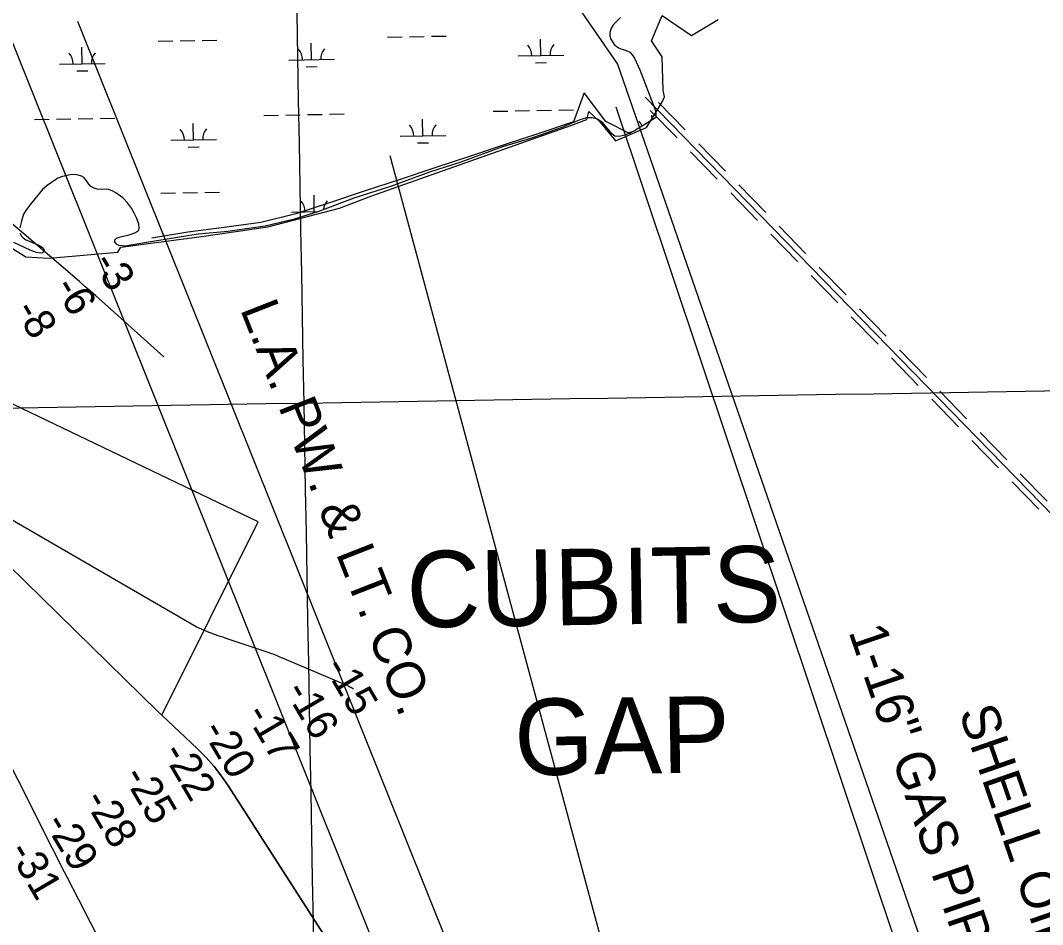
# Model space of a CAD drawing. Extents: x 3914892 to 3953151, y 242587 to 268572.
# Drawn here: x 3939590 to 3941826, y 259377 to 261355 of the extents above; entities that cross this region are included whole.
import ezdxf

# ---------------------------------------------------------------- set-up
doc = ezdxf.new("R2010")
doc.units = 0
for name, color, linetype in [('V-GRID-MAJR', 7, 'Continuous'), ('V-RIVR-EDGE', 7, 'Continuous'), ('V-RIVR-GAP', 7, 'Continuous'), ('V-RIVR-RANG', 7, 'Continuous'), ('V-RRAP-DIKE', 7, 'Continuous'), ('V-RRAP-FSHR', 7, 'Continuous'), ('V-TOPO-DPTH', 7, 'Continuous'), ('V-TOPO-MINR', 7, 'Continuous'), ('V-UTIL-IDEN', 7, 'Continuous'), ('V-UTIL-LINE', 7, 'Continuous'), ('V-WETL-SWMP', 7, 'Continuous')]:
    doc.layers.add(name, color=color, linetype=linetype)

msp = doc.modelspace()

# ---------------------------------------------------------------- linework, layer by layer
at = {"layer": 'V-GRID-MAJR'}
for points in [[(3940428.975, 248401.018), (3940319.725, 254457.832), (3940210.42, 260517.73), (3940101.115, 266577.62), (3940101.059, 266580.712)], [(3918942.3880000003, 260140.297), (3924259.416, 260233.496), (3929576.431, 260327.467), (3934893.433, 260422.212), (3940210.42, 260517.73), (3945527.394, 260614.022), (3950844.353, 260711.087), (3950844.3540000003, 260711.087)]]:
    msp.add_spline(points, degree=3, dxfattribs=at)
at = {"layer": 'V-RIVR-EDGE'}
for points in [[(3940356.2474800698, 260970.12767979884), (3940794.191753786, 261124.67602701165), (3940829.10374867, 261137.76802509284), (3940833.4677480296, 261155.22402253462), (3940858.197077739, 261131.94935927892), (3940891.654406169, 261091.2186985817), (3940960.023729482, 261120.3120276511), (3940981.843726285, 261155.22402253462), (3940994.935724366, 261177.0440193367), (3940999.299723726, 261187.2266845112), (3940996.390390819, 261201.77334904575), (3940994.2083911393, 261275.23400494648), (3940970.9337278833, 261310.14599983), (3940994.2083911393, 261365.42332506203), (3941058.213715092, 261321.78333145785), (3941116.400373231, 261356.69532634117)], [(3939560.530257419, 260863.18542811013), (3939601.4697227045, 260837.69481764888), (3939652.4509436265, 260834.60504668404), (3939803.0772781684, 260847.7365732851), (3939809.256820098, 260858.55077166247), (3939986.146207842, 260881.72405389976), (3940131.365443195, 260903.35245065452), (3940288.171319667, 260944.2919159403), (3940356.242836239, 260970.36185845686)]]:
    msp.add_lwpolyline(points, dxfattribs=at)
at = {"layer": 'V-RRAP-DIKE'}
for points in [[(3942941.2560776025, 259151.36467211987), (3940956.965046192, 261187.10560062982)], [(3941026.768906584, 261097.5817796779), (3940968.1380238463, 261157.73465937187)], [(3941044.67087078, 261115.03174477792), (3940986.039988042, 261175.1846244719)], [(3941114.7167306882, 261007.35296013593), (3941056.084847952, 261067.50583982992)], [(3941132.6186948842, 261024.802925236), (3941073.9868121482, 261084.95580492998)], [(3941202.6645547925, 260917.124140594), (3941144.0326720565, 260977.277020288)], [(3941220.566518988, 260934.5741056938), (3941161.9346362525, 260994.7269853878)], [(3941308.514343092, 260844.3452861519), (3941249.8824603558, 260904.49816584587)], [(3941290.6123788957, 260826.89532105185), (3941231.98049616, 260887.04820074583)], [(3941396.4621671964, 260754.11646660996), (3941337.83028446, 260814.26934630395)], [(3941378.560203, 260736.6665015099), (3941319.928320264, 260796.81938120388)], [(3941484.4099913, 260663.88764706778), (3941425.7781085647, 260724.04052676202)], [(3941466.5080271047, 260646.43768196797), (3941407.876144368, 260706.59056166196)], [(3941572.357815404, 260573.65882752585), (3941513.7259326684, 260633.81170721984)], [(3941554.4558512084, 260556.20886242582), (3941495.823968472, 260616.3617421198)], [(3941660.305639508, 260483.43100798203), (3941601.673756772, 260543.5828876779)], [(3941642.403675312, 260465.98104288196), (3941583.7717925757, 260526.13292257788)], [(3941748.253463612, 260393.20318843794), (3941689.6215808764, 260453.35506813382)], [(3941730.3514994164, 260375.7532233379), (3941671.7196166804, 260435.9051030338)], [(3941836.201287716, 260302.97536889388), (3941777.56940498, 260363.12724859)], [(3941818.29932352, 260285.5254037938), (3941759.667440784, 260345.67728348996)]]:
    msp.add_lwpolyline(points, dxfattribs=at)
at = {"layer": 'V-RRAP-FSHR'}
msp.add_lwpolyline([(3940925.7898332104, 261105.7302865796), (3940870.5634651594, 261133.4090066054), (3940823.340681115, 261196.27851066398), (3940800.136841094, 261132.7393106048), (3940724.2031450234, 261107.55505458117), (3940648.2735449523, 261082.3728465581), (3940572.341896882, 261057.1865425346), (3940496.4102488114, 261032.29924651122), (3940420.4786007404, 261006.81803048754), (3940344.5469526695, 260981.63377446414), (3940268.615304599, 260956.4495184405), (3940192.6836565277, 260931.26526241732), (3940115.619464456, 260912.6100303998), (3940035.722888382, 260901.80683038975), (3939956.418184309, 260891.31697438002), (3939877.5005522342, 260878.21182236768)], dxfattribs=at)
at = {"layer": 'V-TOPO-DPTH'}
for points in [[(3937935.6033522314, 262362.5402043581), (3937946.807549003, 262343.63632242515), (3937958.257643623, 262324.87497740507), (3938066.361568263, 262151.54759992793), (3938132.132563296, 262046.2824872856), (3938198.016029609, 261941.08794122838), (3938264.0682028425, 261835.99924504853), (3938330.2328473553, 261730.98111545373), (3938533.302113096, 261409.237278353), (3938543.3552703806, 261393.41452513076), (3938553.4715195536, 261377.63248157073), (3938563.682406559, 261361.91150250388), (3938573.9563854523, 261346.23123309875), (3938689.531013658, 261170.99052217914), (3938725.5086589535, 261118.47567351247), (3938762.682482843, 261066.8546234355), (3938801.6505746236, 261016.5742712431), (3939215.8425195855, 260521.97311348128), (3939235.1154305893, 260496.93985141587), (3939254.337950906, 260471.8680751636), (3939273.484885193, 260446.73852763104), (3939890.5030939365, 259842.8503603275), (3939899.174331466, 259835.0878290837)], [(3939899.174331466, 259835.0878290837), (3940110.2800000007, 260258.01), (3939485.676288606, 260556.6594979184)], [(3939273.484885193, 260446.73852763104), (3939890.5030939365, 259842.8503603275), (3939899.174331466, 259835.0878290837), (3939977.245341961, 259761.3610688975), (3939995.93333721, 259742.37468959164), (3940013.6277888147, 259722.56399577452), (3940029.8319249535, 259701.51683019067), (3940045.042517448, 259679.64535009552), (3940259.416958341, 259346.02710651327)], [(3939768.654261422, 259332.08815600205), (3939692.0899913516, 259480.36083535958), (3939681.3323571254, 259501.29508046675), (3939670.629942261, 259522.25738085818), (3939660.010356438, 259543.26176417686), (3939649.4459899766, 259564.29420278), (3939601.6381155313, 259659.9443888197), (3939566.333453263, 259728.33550029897)], [(3939768.654261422, 259332.08815600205), (3939692.0899913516, 259480.36083535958), (3939681.3323571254, 259501.29508046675), (3939670.629942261, 259522.25738085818), (3939660.010356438, 259543.26176417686), (3939649.4459899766, 259564.29420278), (3939601.6381155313, 259659.9443888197), (3939566.333453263, 259728.33550029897)]]:
    msp.add_lwpolyline(points, dxfattribs=at)
at = {"layer": 'V-TOPO-MINR'}
for points in [[(3939903.7800000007, 260619.13), (3939766.9304156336, 260741.46724377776), (3939755.026493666, 260752.03635902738), (3939743.0751896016, 260762.5512495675), (3939731.0528123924, 260772.98480304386), (3939718.983053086, 260783.36413181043), (3939193.1441723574, 261232.46224556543)], [(3940110.2800000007, 260258.01), (3939485.676288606, 260556.6594979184)], [(3940259.416958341, 259346.02710651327), (3940045.042517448, 259679.64535009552), (3940029.8319249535, 259701.51683019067), (3940013.6277888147, 259722.56399577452), (3939995.93333721, 259742.37468959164), (3939977.245341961, 259761.3610688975), (3939899.174331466, 259835.0878290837), (3939890.5030939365, 259842.8503603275), (3939273.484885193, 260446.73852763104)], [(3940318.31, 259892.08000000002), (3940314.3937941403, 259894.5625426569), (3940312.4091833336, 259895.75328992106), (3940308.3169462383, 259897.9003167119), (3940306.2093199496, 259898.85659623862), (3940177.4224712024, 259953.51548022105), (3940172.00488143, 259955.82833565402), (3940166.5939002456, 259958.15646144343), (3940161.1928319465, 259960.50749276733), (3940155.798372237, 259962.87379444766), (3940150.379223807, 259965.17489716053), (3940144.9206192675, 259967.37398063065), (3940139.4028305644, 259969.4200352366), (3940133.8455857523, 259971.3640705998), (3940042.2333125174, 260001.9849008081), (3940032.405484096, 260005.32902063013), (3940022.60267381, 260008.74372962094), (3940012.8373907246, 260012.26432236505), (3940003.097125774, 260015.85550427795), (3939974.735562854, 260028.50245078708), (3939542.998862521, 260277.52856744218)], [(3939768.654261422, 259332.08815600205), (3939692.0899913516, 259480.36083535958), (3939681.3323571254, 259501.29508046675), (3939670.629942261, 259522.25738085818), (3939660.010356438, 259543.26176417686), (3939649.4459899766, 259564.29420278), (3939601.6381155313, 259659.9443888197), (3939566.333453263, 259728.33550029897)]]:
    msp.add_lwpolyline(points, dxfattribs=at)
at = {"layer": 'V-UTIL-LINE'}
for p, q in [((3941072.986, 257567.442), (3939526.299, 261421.028)), ((3941262.278, 257498.559), (3939715.592, 261352.14800000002)), ((3942171.498, 257345.774), (3940893.606, 261165.00400000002)), ((3941339.742, 257565.166), (3940398.835, 261058.278))]:
    msp.add_line(p, q, dxfattribs=at)
msp.add_lwpolyline([(3937257.69907959, 266529.8389520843), (3940896.284, 261258.97), (3942305.4820000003, 257189.557), (3945242.894, 251786.949), (3947661.3890917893, 248530.41995604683)], dxfattribs=at)
at = {"layer": 'V-WETL-SWMP'}
for p, q in [((3940393.176292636, 261318.2527012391), (3940425.1711721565, 261318.8251385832)), ((3940441.168611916, 261319.1113572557), (3940473.1634914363, 261319.68379459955)), ((3940489.1609311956, 261319.9700132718), (3940521.1558107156, 261320.54245061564)), ((3940728.7972833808, 261277.82004355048), (3940728.1532913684, 261313.8142830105)), ((3939725.1419090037, 261259.8631133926), (3939724.497916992, 261295.8573528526)), ((3939891.348605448, 261309.27423616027), (3939923.3434849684, 261309.84667350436)), ((3939939.3409247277, 261310.13289217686), (3939971.3358042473, 261310.70532952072)), ((3939987.333244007, 261310.99154819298), (3940019.328123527, 261311.5639855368)), ((3940226.9695961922, 261268.84157847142), (3940226.3256041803, 261304.83581793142)), ((3940176.977596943, 261267.9471451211), (3940276.9615954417, 261269.73601182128)), ((3940678.8052841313, 261276.92561020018), (3940778.78928263, 261278.71447690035)), ((3939675.1499097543, 261258.96868004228), (3939775.1339082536, 261260.75754674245)), ((3940215.2475563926, 261253.1983836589), (3940239.2437160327, 261253.6277116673)), ((3940717.0752435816, 261262.17684873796), (3940741.071403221, 261262.60617674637)), ((3939713.4198692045, 261244.21991858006), (3939737.416028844, 261244.64924658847)), ((3940624.11829016, 261155.85695997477), (3940656.11316968, 261156.42939731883)), ((3940672.11060944, 261156.7156159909), (3940704.1054889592, 261157.28805333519)), ((3940720.1029287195, 261157.57427200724), (3940752.097808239, 261158.1467093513)), ((3940768.0952479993, 261158.43292802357), (3940800.090127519, 261159.00536536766)), ((3939620.462915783, 261137.90002981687), (3939652.457795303, 261138.47246716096)), ((3939668.4552350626, 261138.758685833), (3939700.4501145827, 261139.33112317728)), ((3939716.4475543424, 261139.61734184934), (3939748.4424338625, 261140.1897791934)), ((3939764.439873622, 261140.4759978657), (3939796.434753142, 261141.04843520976)), ((3940122.2906029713, 261146.8784948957), (3940154.2854824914, 261147.45093223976)), ((3940170.282922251, 261147.73715091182), (3940202.277801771, 261148.30958825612)), ((3940218.275241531, 261148.59580692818), (3940250.270121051, 261149.16824427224)), ((3940266.267560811, 261149.4544629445), (3940298.262440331, 261150.0269002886)), ((3940470.458733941, 261102.35763464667), (3940469.8147419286, 261138.35187410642)), ((3940971.828457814, 261136.93275451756), (3940971.642429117, 261147.3303391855)), ((3939968.6310467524, 261093.37916956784), (3939967.98705474, 261129.37340902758)), ((3939918.6390475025, 261092.4847362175), (3940018.6230460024, 261094.2736029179)), ((3940420.466734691, 261101.46320129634), (3940520.4507331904, 261103.25206799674)), ((3940922.29442188, 261110.4416663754), (3940927.821896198, 261110.5405613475)), ((3939956.9090069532, 261077.73597475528), (3939980.9051665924, 261078.1653027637)), ((3940458.7366941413, 261086.71443983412), (3940482.732853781, 261087.14376784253)), ((3939897.299717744, 260976.65246915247), (3939929.294597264, 260977.22490649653)), ((3939945.2920370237, 260977.51112516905), (3939977.2869165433, 260978.08356251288)), ((3939993.2843563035, 260978.36978118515), (3940025.2792358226, 260978.942218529)), ((3940232.920708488, 260936.2198114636), (3940232.276716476, 260972.2140509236)), ((3940182.928709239, 260935.32537811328), (3940241.469185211, 260936.3727567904))]:
    msp.add_line(p, q, dxfattribs=at)
for points in [[(3940902.921, 261360.817), (3940894.651, 261353.166), (3940887.59, 261345.86500000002), (3940882.708, 261337.578), (3940879.7090000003, 261327.986), (3940879.506, 261321.252), (3940882.086, 261313.707), (3940889.102, 261302.05000000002), (3940898.2460000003, 261294.75400000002), (3940905.853, 261291.68), (3940913.578, 261289.527), (3940923.381, 261285.008), (3940928.474, 261279.698), (3940933.514, 261271.787), (3940945.032, 261246.237), (3940977.9220000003, 261161.116), (3940980.301, 261150.812), (3940980.11, 261143.77300000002), (3940979.117, 261141.748), (3940973.3030000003, 261137.858), (3940933.8850000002, 261113.124), (3940912.223, 261103.894), (3940899.6520000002, 261100.817), (3940890.1350000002, 261101.832), (3940883.985, 261106.795), (3940874.855, 261117.761), (3940864.287, 261130.353), (3940852.666, 261138.472), (3940841.0840000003, 261141.548), (3940829.149, 261141.859), (3940815.99, 261138.149), (3940805.2970000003, 261133.921), (3940794.622, 261129.23500000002), (3940778.2320000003, 261122.03900000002), (3940762.4020000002, 261116.24000000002), (3940749.883, 261111.79), (3940729.061, 261104.578), (3940705.8200000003, 261096.66400000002), (3940644.448, 261078.434), (3940553.256, 261044.396), (3940485.046, 261022.812), (3940399.938, 260991.71300000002), (3940319.202, 260965.496), (3940240.92, 260936.16700000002), (3940186.9, 260919.427), (3940125.6240000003, 260904.801), (3940043.375, 260893.008), (3939978.823, 260886.853), (3939865.734, 260868.856), (3939818.991, 260860.931), (3939805.632, 260862.397), (3939800.969, 260864.55000000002), (3939798.346, 260866.548), (3939796.248, 260870.592), (3939796.745, 260874.489), (3939800.205, 260878.431), (3939808.5, 260881.14800000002), (3939818.284, 260883.333), (3939827.878, 260885.885), (3939839.859, 260889.769), (3939847.026, 260893.581), (3939848.839, 260896.20200000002), (3939849.889, 260900.29200000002), (3939848.644, 260909.16400000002), (3939844.7600000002, 260921.146), (3939838.468, 260933.09100000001), (3939832.566, 260943.746), (3939823.873, 260955.285)], [(3939823.873, 260955.285), (3939813.8880000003, 260966.434), (3939798.5360000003, 260977.317), (3939792.182, 260981.111), (3939783.24, 260984.497), (3939777.3000000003, 260985.334), (3939767.491, 260984.816), (3939758.032, 260985.6), (3939751.332, 260987.722), (3939743.864, 260991.685), (3939739.7120000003, 260996.809), (3939733.6580000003, 261005.239), (3939728.757, 261010.907), (3939723.707, 261014.166), (3939716.454, 261016.094), (3939709.022, 261017.65), (3939698.475, 261016.93600000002), (3939681.861, 261013.16700000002), (3939671.917, 261009.313), (3939657.791, 261000.211), (3939648.626, 260993.775), (3939638.383, 260985.101), (3939612.366, 260953.778), (3939603.29, 260941.41700000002), (3939596.597, 260930.758), (3939592.1890000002, 260915.874), (3939588.705, 260901.189)], [(3939589.074, 260888.969), (3939591.5670000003, 260883.265), (3939595.52, 260879.064), (3939601.698, 260874.711), (3939611.386, 260870.967), (3939630.024, 260863.282), (3939637.683, 260858.951), (3939640.693, 260855.847), (3939641.8850000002, 260850.494), (3939641.36, 260848.448), (3939638.063, 260845.991), (3939633.444, 260845.181), (3939624.901, 260846.719), (3939611.117, 260851.884), (3939575.2970000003, 260868.943)]]:
    msp.add_lwpolyline(points, dxfattribs=at)
for centre, radius, start, end in [((3940171.7270061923, 261268.32808319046), 35.24628790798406, 0.25317973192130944, 41.79683806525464), ((3940282.1951989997, 261270.304528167), 35.24628790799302, 140.25317672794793, 181.79683506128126), ((3940673.5546933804, 261277.30654826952), 35.24628790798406, 0.25317973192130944, 41.79683806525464), ((3940784.0228861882, 261279.28299324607), 35.24628790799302, 140.25317672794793, 181.79683506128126), ((3939669.899319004, 261259.34961811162), 35.24628790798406, 0.25317973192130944, 41.79683806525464), ((3939780.367511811, 261261.32606308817), 35.24628790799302, 140.25317672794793, 181.79683506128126), ((3940917.0438311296, 261110.82260444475), 35.24628790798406, 20.64917184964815, 41.79683806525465), ((3939913.388456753, 261092.86567428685), 35.24628790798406, 0.25317973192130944, 41.79683806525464), ((3940023.85664956, 261094.84211926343), 35.24628790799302, 140.25317672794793, 181.79683506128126), ((3940415.216143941, 261101.84413936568), 35.24628790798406, 0.25317973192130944, 41.79683806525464), ((3940525.684336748, 261103.82058434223), 35.24628790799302, 140.25317672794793, 181.79683506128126), ((3940177.678118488, 260935.70631618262), 35.24628790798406, 0.25317973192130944, 41.79683806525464), ((3940288.1463112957, 260937.68276115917), 35.24628790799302, 140.2531767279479, 175.08265987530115)]:
    msp.add_arc(centre, radius, start, end, dxfattribs=at)

# ---------------------------------------------------------------- texts
at = {"layer": 'V-RIVR-GAP'}
for s, p in [('CUBITS', (3940436.0483540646, 260026.24408314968)), ('GAP', (3940671.7567540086, 259702.98355042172))]:
    msp.add_text(s, height=166.99966400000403, rotation=0.8953166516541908, dxfattribs=at).set_placement(p)
at = {"layer": 'V-RIVR-RANG'}
for s, height, rotation, p in [('-3', 67, 300.6083257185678, (3939746.2103890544, 260825.65121835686)), ('-6', 67, 300.88811111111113, (3939661.7547075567, 260771.53916007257)), ('-8', 67, 300.88811111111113, (3939575.5398781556, 260720.86789619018)), ('-15', 67, 300.21832571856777, (3940252.8596074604, 259940.12139476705)), ('-16', 67.00000000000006, 300.50005555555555, (3940167.177219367, 259887.91003760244)), ('-17', 67.00000000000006, 300.50005555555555, (3940080.749346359, 259837.6064943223)), ('-20', 67.00000000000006, 300.50005555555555, (3939985.631363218, 259802.0567978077)), ('-22', 67.00000000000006, 300.50005555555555, (3939898.4062140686, 259753.1067578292)), ('-25', 67.00000000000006, 300.50005555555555, (3939812.653727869, 259701.65663781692)), ('-28', 67.00000000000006, 300.50005555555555, (3939726.9012416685, 259650.20651780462)), ('-29', 67.00000000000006, 300.50005555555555, (3939641.0148770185, 259598.9836777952)), ('-31', 67.00000000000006, 300.50005555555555, (3939561.4207995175, 259537.07967764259))]:
    msp.add_text(s, height=height, rotation=rotation, dxfattribs=at).set_placement(p)
at = {"layer": 'V-UTIL-IDEN'}
for s, height, rotation, p in [('L.A. PW. & LT. CO.', 82.99983200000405, 291.4177770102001, (3940070.0331512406, 260723.26222377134)), ('1-16" GAS PIPELINE', 82.99983200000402, 288.90900813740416, (3941401.208545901, 260018.03314976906)), ('SHELL OIL CO.', 82.99983200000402, 289.0439256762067, (3941642.5110820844, 259841.68528137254))]:
    msp.add_text(s, height=height, rotation=rotation, dxfattribs=at).set_placement(p)

doc.saveas('drawing.dxf')
